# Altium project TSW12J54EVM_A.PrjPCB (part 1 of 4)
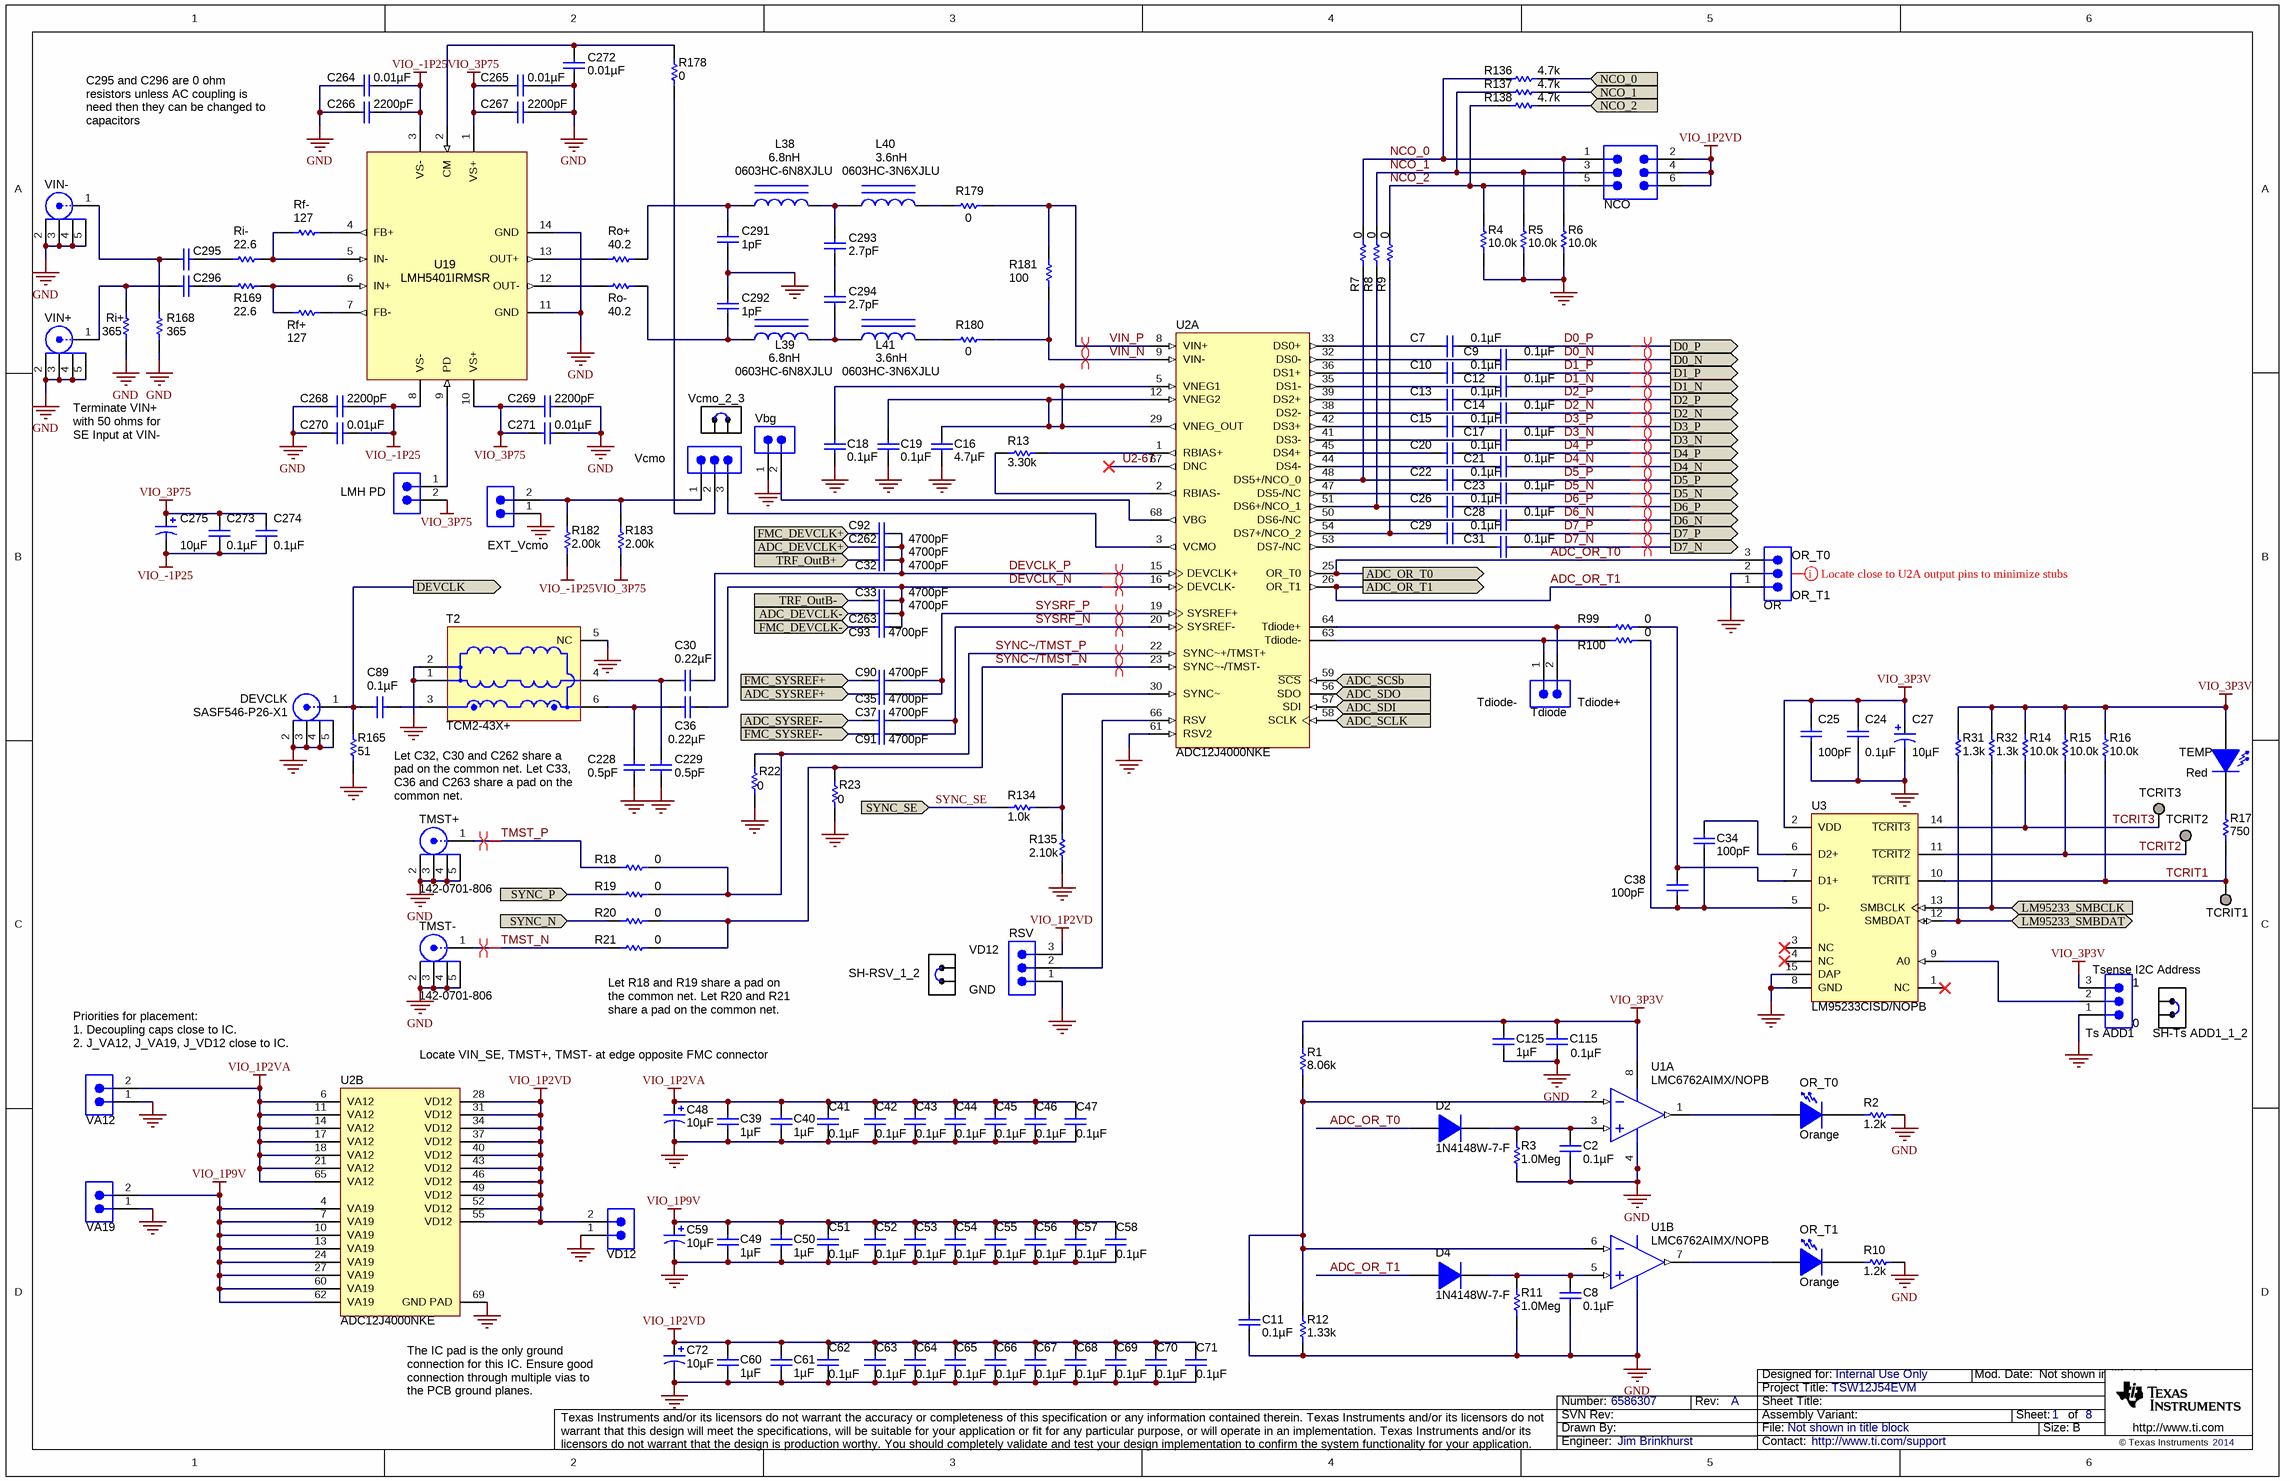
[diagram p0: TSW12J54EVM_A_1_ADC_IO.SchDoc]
CopyrightYear: 2014; Drawn By: Jim Brinkhurst; PCB_LAYOUT: Bob Holtz; PCB_REV: A; PRJ_Customer: Internal Use Only; PRJ_ENGINEER: Jim Brinkhurst; PRJ_NUMBER: 6586307; PRJ_Title: TSW12J54EVM; SCH_Rev: A; TechSupport: http://www.ti.com/support
8 sheets, 655 parts. Net scope: global (net labels, ports and power ports of the same name join across sheets).
Board file: TSW12J54EVM_A.PcbDoc
Sheets:
  TSW12J54EVM_A_1_ADC_IO.SchDoc
  TSW12J54EVM_A_2_FMC.SchDoc
  TSW12J54EVM_A_3_TRF3765.SchDoc
  TSW12J54EVM_A_4_LMK04828.SchDoc
  TSW12J54EVM_A_5_Power.SchDoc
  TSW12J54EVM_A_6_Power.SchDoc
  TSW12J54EVM_A_7_InterfaceControl.SchDoc
  TSW12J54EVM_A_8_Hardware.SchDoc

## Sheet TSW12J54EVM_A_1_ADC_IO.SchDoc
size 431 x 279 mm; Date: Not shown in title block; ApprovedBy: Not shown in title block; CheckedBy: Not shown in title block; Author: Not shown in title block; CompanyName: Not shown in title block; Engineer: Not shown in title block; Organization: Not shown in title block; Address1: Not shown in title block; Address2: Not shown in title block; Address3: Not shown in title block; Address4: Not shown in title block; DocumentNumber: 1; Revision: Use project parameter SCH_Rev; SheetNumber: 1; SheetTotal: 8; PageSetup: Record=PageOptions¦CenterHorizontal=True¦CenterVertical=True¦PrintScale=1.32¦XCorrection=1.00¦YCorrection=1.00¦PrintKind=0¦BorderSize=5000000¦LeftOffset=0¦BottomOffset=0¦Orientation=2¦PaperLength=1000¦PaperWidth=1000¦Scale=100¦PaperSource=15¦PrintQuality=600¦MediaType=1¦DitherType=10¦PaperKind=Letter¦PrintScaleMode=1

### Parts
C2  ValueDisplayed: 0.1µF  [0402L]  (hidden comment: GRM155R71A104KA01D)
C7  ValueDisplayed: 0.1µF  [0201]  (hidden comment: C0603X5R0J104K)
C8  ValueDisplayed: 0.1µF  [0402L]  (hidden comment: GRM155R71A104KA01D)
C9  ValueDisplayed: 0.1µF  [0201]  (hidden comment: C0603X5R0J104K)
C10  ValueDisplayed: 0.1µF  [0201]  (hidden comment: C0603X5R0J104K)
C11  ValueDisplayed: 0.1µF  [0402L]  (hidden comment: GRM155R71A104KA01D)
C12  ValueDisplayed: 0.1µF  [0201]  (hidden comment: C0603X5R0J104K)
C13  ValueDisplayed: 0.1µF  [0201]  (hidden comment: C0603X5R0J104K)
C14  ValueDisplayed: 0.1µF  [0201]  (hidden comment: C0603X5R0J104K)
C15  ValueDisplayed: 0.1µF  [0201]  (hidden comment: C0603X5R0J104K)
C16  ValueDisplayed: 4.7µF  [0402L]  (hidden comment: C1005X5R0J475M050BC)
C17  ValueDisplayed: 0.1µF  [0201]  (hidden comment: C0603X5R0J104K)
C18  ValueDisplayed: 0.1µF  [0402L]  (hidden comment: C1005X5R1A104K)
C19  ValueDisplayed: 0.1µF  [0402L]  (hidden comment: C1005X5R1A104K)
C20  ValueDisplayed: 0.1µF  [0201]  (hidden comment: C0603X5R0J104K)
C21  ValueDisplayed: 0.1µF  [0201]  (hidden comment: C0603X5R0J104K)
C22  ValueDisplayed: 0.1µF  [0201]  (hidden comment: C0603X5R0J104K)
C23  ValueDisplayed: 0.1µF  [0201]  (hidden comment: C0603X5R0J104K)
C24  ValueDisplayed: 0.1µF  [0603L]  (hidden comment: 0603YC104JAT2A)
C25  ValueDisplayed: 100pF  [0603L]  (hidden comment: 06035A101JAT2A)
C26  ValueDisplayed: 0.1µF  [0201]  (hidden comment: C0603X5R0J104K)
C27  ValueDisplayed: 10µF  [3528-21]  (hidden comment: 293D106X0010B2TE3)
C28  ValueDisplayed: 0.1µF  [0201]  (hidden comment: C0603X5R0J104K)
C29  ValueDisplayed: 0.1µF  [0201]  (hidden comment: C0603X5R0J104K)
C30  ValueDisplayed: 0.22µF  [0201]  (hidden comment: C0603X5R0J224M)
C31  ValueDisplayed: 0.1µF  [0201]  (hidden comment: C0603X5R0J104K)
C32  ValueDisplayed: 4700pF  [0201]  (hidden comment: GRM033R61A472KA01D)
C33  ValueDisplayed: 4700pF  [0201]  (hidden comment: GRM033R61A472KA01D)
C34  ValueDisplayed: 100pF  [0603L]  (hidden comment: 06035A101JAT2A)
C35  ValueDisplayed: 4700pF  [0201]  (hidden comment: GRM033R61A472KA01D)
C36  ValueDisplayed: 0.22µF  [0201]  (hidden comment: C0603X5R0J224M)
C37  ValueDisplayed: 4700pF  [0201]  (hidden comment: GRM033R61A472KA01D)
C38  ValueDisplayed: 100pF  [0603L]  (hidden comment: 06035A101JAT2A)
C39  ValueDisplayed: 1µF  [0603L]  (hidden comment: C1608X5R1A105K)
C40  ValueDisplayed: 1µF  [0603L]  (hidden comment: C1608X5R1A105K)
C41  ValueDisplayed: 0.1µF  [0201]  (hidden comment: C0603X5R0J104K)
C42  ValueDisplayed: 0.1µF  [0201]  (hidden comment: C0603X5R0J104K)
C43  ValueDisplayed: 0.1µF  [0201]  (hidden comment: C0603X5R0J104K)
C44  ValueDisplayed: 0.1µF  [0201]  (hidden comment: C0603X5R0J104K)
C45  ValueDisplayed: 0.1µF  [0201]  (hidden comment: C0603X5R0J104K)
C46  ValueDisplayed: 0.1µF  [0201]  (hidden comment: C0603X5R0J104K)
C47  ValueDisplayed: 0.1µF  [0201]  (hidden comment: C0603X5R0J104K)
C48  ValueDisplayed: 10µF  [3528-21]  (hidden comment: 293D106X0010B2TE3)
C49  ValueDisplayed: 1µF  [0603L]  (hidden comment: C1608X5R1A105K)
C50  ValueDisplayed: 1µF  [0603L]  (hidden comment: C1608X5R1A105K)
C51  ValueDisplayed: 0.1µF  [0201]  (hidden comment: C0603X5R0J104K)
C52  ValueDisplayed: 0.1µF  [0201]  (hidden comment: C0603X5R0J104K)
C53  ValueDisplayed: 0.1µF  [0201]  (hidden comment: C0603X5R0J104K)
C54  ValueDisplayed: 0.1µF  [0201]  (hidden comment: C0603X5R0J104K)
C55  ValueDisplayed: 0.1µF  [0201]  (hidden comment: C0603X5R0J104K)
C56  ValueDisplayed: 0.1µF  [0201]  (hidden comment: C0603X5R0J104K)
C57  ValueDisplayed: 0.1µF  [0201]  (hidden comment: C0603X5R0J104K)
C58  ValueDisplayed: 0.1µF  [0201]  (hidden comment: C0603X5R0J104K)
C59  ValueDisplayed: 10µF  [3528-21]  (hidden comment: 293D106X0010B2TE3)
C60  ValueDisplayed: 1µF  [0603L]  (hidden comment: C1608X5R1A105K)
C61  ValueDisplayed: 1µF  [0603L]  (hidden comment: C1608X5R1A105K)
C62  ValueDisplayed: 0.1µF  [0201]  (hidden comment: C0603X5R0J104K)
C63  ValueDisplayed: 0.1µF  [0201]  (hidden comment: C0603X5R0J104K)
C64  ValueDisplayed: 0.1µF  [0201]  (hidden comment: C0603X5R0J104K)
C65  ValueDisplayed: 0.1µF  [0201]  (hidden comment: C0603X5R0J104K)
C66  ValueDisplayed: 0.1µF  [0201]  (hidden comment: C0603X5R0J104K)
C67  ValueDisplayed: 0.1µF  [0201]  (hidden comment: C0603X5R0J104K)
C68  ValueDisplayed: 0.1µF  [0201]  (hidden comment: C0603X5R0J104K)
C69  ValueDisplayed: 0.1µF  [0201]  (hidden comment: C0603X5R0J104K)
C70  ValueDisplayed: 0.1µF  [0201]  (hidden comment: C0603X5R0J104K)
C71  ValueDisplayed: 0.1µF  [0201]  (hidden comment: C0603X5R0J104K)
C72  ValueDisplayed: 10µF  [3528-21]  (hidden comment: 293D106X0010B2TE3)
C89  ValueDisplayed: 0.1µF  [0402L]  (hidden comment: C1005X5R1A104K)
C90  ValueDisplayed: 4700pF  [0201]  (hidden comment: GRM033R61A472KA01D)
C91  ValueDisplayed: 4700pF  [0201]  (hidden comment: GRM033R61A472KA01D)
C92  ValueDisplayed: 4700pF  [0201]  (hidden comment: GRM033R61A472KA01D)
C93  ValueDisplayed: 4700pF  [0201]  (hidden comment: GRM033R61A472KA01D)
C115  ValueDisplayed: 0.1µF  [0603L]  (hidden comment: 0603YC104JAT2A)
C125  ValueDisplayed: 1µF  [0603L]  (hidden comment: C1608X5R1A105K)
C228  ValueDisplayed: 0.5pF  [0402L]  (hidden comment: 500R07S0R5BV4T)
C229  ValueDisplayed: 0.5pF  [0402L]  (hidden comment: 500R07S0R5BV4T)
C262  ValueDisplayed: 4700pF  [0201]  (hidden comment: GRM033R61A472KA01D)
C263  ValueDisplayed: 4700pF  [0201]  (hidden comment: GRM033R61A472KA01D)
C264  ValueDisplayed: 0.01µF  [0306]  (hidden comment: LLL185R71E103MA01L)
C265  ValueDisplayed: 0.01µF  [0306]  (hidden comment: LLL185R71E103MA01L)
C266  ValueDisplayed: 2200pF  [0306]  (hidden comment: LLL185R71H222MA01L)
C267  ValueDisplayed: 2200pF  [0306]  (hidden comment: LLL185R71H222MA01L)
C268  ValueDisplayed: 2200pF  [0306]  (hidden comment: LLL185R71H222MA01L)
C269  ValueDisplayed: 2200pF  [0306]  (hidden comment: LLL185R71H222MA01L)
C270  ValueDisplayed: 0.01µF  [0306]  (hidden comment: LLL185R71E103MA01L)
C271  ValueDisplayed: 0.01µF  [0306]  (hidden comment: LLL185R71E103MA01L)
C272  ValueDisplayed: 0.01µF  [0402L]  (hidden comment: C1005X7R1E103K)
C273  ValueDisplayed: 0.1µF  [0402L]  (hidden comment: C1005X5R1A104K)
C274  ValueDisplayed: 0.1µF  [0402L]  (hidden comment: C1005X5R1A104K)
C275  ValueDisplayed: 10µF  [3216-18]  (hidden comment: TPSA106K010R0900)
C291  ValueDisplayed: 1pF  [0402L]  (hidden comment: GRM1555C1H1R0CA01D)
C292  ValueDisplayed: 1pF  [0402L]  (hidden comment: GRM1555C1H1R0CA01D)
C293  ValueDisplayed: 2.7pF  [0402L]  (hidden comment: GRM1555C1H2R7CA01D)
C294  ValueDisplayed: 2.7pF  [0402L]  (hidden comment: GRM1555C1H2R7CA01D)
C295  Used in BOM report  [0402L]  (value not drawn)
C296  Used in BOM report  [0402L]  (value not drawn)
D2  1N4148W-7-F  [SOD-123]
D4  1N4148W-7-F  [SOD-123]
DEVCLK  SASF546-P26-X1  [CONN_LTI_SASF546-P26-X1]
EXT_Vcmo  TSW-102-07-G-S  [TSW-102-07-G-S]  (value not drawn)
L38  0603HC-6N8XJLU  ValueDisplayed: 6.8nH  [0603HC]
L39  0603HC-6N8XJLU  ValueDisplayed: 6.8nH  [0603HC]
L40  0603HC-3N6XJLU  ValueDisplayed: 3.6nH  [0603HC]
L41  0603HC-3N6XJLU  ValueDisplayed: 3.6nH  [0603HC]
LMH_PD  TSW-102-07-G-S  [TSW-102-07-G-S]  (value not drawn)
NCO  TSW-103-07-G-D  [TSW-103-07-G-D]  (value not drawn)
OR  TSW-103-07-G-S  [TSW-103-07-G-S]  (value not drawn)
OR_T0  value Orange  [LED_LTST-C190]  (hidden comment: LTST-C190KFKT)
OR_T1  value Orange  [LED_LTST-C190]  (hidden comment: LTST-C190KFKT)
R1  value 8.06k  [0402L]  (hidden comment: CRCW04028K06FKED)
R2  value 1.2k  [0402L]  (hidden comment: CRCW04021K20JNED)
R3  value 1.0Meg  [0402L]  (hidden comment: CRCW04021M00JNED)
R4  value 10.0k  [0603L]  (hidden comment: CRCW060310K0FKEA)
R5  value 10.0k  [0603L]  (hidden comment: CRCW060310K0FKEA)
R6  value 10.0k  [0603L]  (hidden comment: CRCW060310K0FKEA)
R7  value 0  [0201]  (hidden comment: ERJ-1GE0R00C)
R8  value 0  [0201]  (hidden comment: ERJ-1GE0R00C)
R9  value 0  [0201]  (hidden comment: ERJ-1GE0R00C)
R10  value 1.2k  [0402L]  (hidden comment: CRCW04021K20JNED)
R11  value 1.0Meg  [0402L]  (hidden comment: CRCW04021M00JNED)
R12  value 1.33k  [0402L]  (hidden comment: CRCW04021K33FKED)
R13  value 3.30k  [0603L]  (hidden comment: RG1608P-332-B-T5)
R14  value 10.0k  [0603L]  (hidden comment: CRCW060310K0FKEA)
R15  value 10.0k  [0603L]  (hidden comment: CRCW060310K0FKEA)
R16  value 10.0k  [0603L]  (hidden comment: CRCW060310K0FKEA)
R17  value 750  [0603L]  (hidden comment: RC0603JR-07750RL)
R18  value 0  [0201]  (hidden comment: ERJ-1GE0R00C)
R19  value 0  [0201]  (hidden comment: ERJ-1GE0R00C)
R20  value 0  [0201]  (hidden comment: ERJ-1GE0R00C)
R21  value 0  [0201]  (hidden comment: ERJ-1GE0R00C)
R22  value 0  [0201]  (hidden comment: ERJ-1GE0R00C)
R23  value 0  [0201]  (hidden comment: ERJ-1GE0R00C)
R31  value 1.3k  [0603L]  (hidden comment: RC0603JR-071K3L)
R32  value 1.3k  [0603L]  (hidden comment: RC0603JR-071K3L)
R99  value 0  [0603L]  (hidden comment: ERJ-3GEY0R00V)
R100  value 0  [0603L]  (hidden comment: ERJ-3GEY0R00V)
R134  value 1.0k  [0603L]  (hidden comment: RC0603JR-071KL)
R135  value 2.10k  [0603L]  (hidden comment: CRCW06032K10FKEA)
R136  value 4.7k  [0603L]  (hidden comment: CRCW06034K70JNEA)
R137  value 4.7k  [0603L]  (hidden comment: CRCW06034K70JNEA)
R138  value 4.7k  [0603L]  (hidden comment: CRCW06034K70JNEA)
R165  value 51  [0402L]  (hidden comment: CRCW040251R0JNED)
R168  ValueDisplayed: 365  [0402L]  (hidden comment: CRCW0402365RFKED)
R169  ValueDisplayed: 22.6  [0402L]  (hidden comment: CRCW040222R6FKED)
R178  value 0  [0402L]  (hidden comment: CRCW04020000Z0ED)
R179  value 0  [0402L]  (hidden comment: CRCW04020000Z0ED)
R180  value 0  [0402L]  (hidden comment: CRCW04020000Z0ED)
R181  value 100  [0402L]  (hidden comment: CRCW0402100RFKED)
R182  ValueDisplayed: 2.00k  [0402L]  (hidden comment: CRCW04022K00FKED)
R183  ValueDisplayed: 2.00k  [0402L]  (hidden comment: CRCW04022K00FKED)
Rf+  ValueDisplayed: 127  [0402L]  (hidden comment: CRCW0402127RFKED)
Rf-  ValueDisplayed: 127  [0402L]  (hidden comment: CRCW0402127RFKED)
Ri+  ValueDisplayed: 365  [0402L]  (hidden comment: CRCW0402365RFKED)
Ri-  ValueDisplayed: 22.6  [0402L]  (hidden comment: CRCW040222R6FKED)
Ro+  value 40.2  [0402L]  (hidden comment: CRCW040240R2FKED)
Ro-  value 40.2  [0402L]  (hidden comment: CRCW040240R2FKED)
RSV  TSW-103-07-G-S  [TSW-103-07-G-S]  (value not drawn)
SH-RSV_1_2  969102-0000-DA  [SNT-100-BK-G]  (value not drawn)
SH-Ts_ADD1_1_2  969102-0000-DA  [SNT-100-BK-G]  (value not drawn)
T2  TCM2-43X+  [Mini-Circuits-DB1627]
TCRIT1  TESTPOINT  [TESTPOINT]  (value not drawn)  (no BOM)
TCRIT2  TESTPOINT  [TESTPOINT]  (value not drawn)  (no BOM)
TCRIT3  TESTPOINT  [TESTPOINT]  (value not drawn)  (no BOM)
Tdiode  TSW-102-07-G-S  [TSW-102-07-G-S]  (value not drawn)
TEMP  value Red  [LED_LTST-C170]  (hidden comment: LTST-C170KRKT)
TMST+  142-0701-806  [Johnson_142-0701-80x]
TMST-  142-0701-806  [Johnson_142-0701-80x]
Ts_ADD1  TSW-103-07-G-S  [TSW-103-07-G-S]  (value not drawn)
U1  LMC6762AIMX/NOPB  [M08A_L]  (parts A,B of 2)
U2  ADC12J4000NKE  [RLY0068A]  (parts A,B of 2)
U3  LM95233CISD/NOPB  [SDA14B]
U19  LMH5401IRMSR  [RMS0014A]
VA12  TSW-102-07-G-S  [TSW-102-07-G-S]  (value not drawn)
VA19  TSW-102-07-G-S  [TSW-102-07-G-S]  (value not drawn)
Vbg  TSW-102-07-G-S  [TSW-102-07-G-S]  (value not drawn)
Vcmo  TSW-103-07-G-S  [TSW-103-07-G-S]  (value not drawn)
Vcmo_2_3  969102-0000-DA  [SNT-100-BK-G]  (value not drawn)
VD12  TSW-102-07-G-S  [TSW-102-07-G-S]  (value not drawn)
VIN+  142-0701-231  [Johnson_142-0701-231]  (value not drawn)
VIN-  142-0701-231  [Johnson_142-0701-231]  (value not drawn)

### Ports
ADC_DEVCLK+ (in), ADC_DEVCLK- (in), ADC_OR_T0 (out), ADC_OR_T1 (out), ADC_SCLK (in), ADC_SCSb (in), ADC_SDI (in), ADC_SDO (out), ADC_SYSREF+, ADC_SYSREF-, D0_N (out), D0_P (out), D1_N (out), D1_P (out), D2_N (out), D2_P (out), D3_N (out), D3_P (out), D4_N (out), D4_P (out), D5_N (out), D5_P (out), D6_N (out), D6_P (out), D7_N (out), D7_P (out), DEVCLK (out), FMC_DEVCLK+ (in), FMC_DEVCLK- (in), FMC_SYSREF+, FMC_SYSREF-, LM95233_SMBCLK (in), LM95233_SMBDAT (bidir), NCO_0 (in), NCO_1 (in), NCO_2 (in), SYNC_N (in), SYNC_P (in), SYNC_SE (in), TRF_OutB+ (in), TRF_OutB- (in)

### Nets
GND: C2.2 C8.2 C11.2 C16.1 C18.1 C19.1 C24.2 C25.2 C27.2(-) C39.2 C40.2 C41.1 C42.1 C43.1 C44.1 C45.1 C46.1 C47.1 C48.2(-) C49.2 C50.2 C51.1 C52.1 C53.1 C54.1 C55.1 C56.1 C57.1 C58.1 C59.2(-) C60.2 C61.2 C62.1 C63.1 C64.1 C65.1 C66.1 C67.1 C68.1 C69.1 C70.1 C71.1 C72.2(-) C115.2 C125.2 C228.2 C229.2 C264.1 C265.2 C266.2 C267.1 C268.2 C269.1 C270.1 C271.2 C272.1 C291.2 C292.1 DEVCLK.2 DEVCLK.3 DEVCLK.4 DEVCLK.5 EXT_Vcmo.1 OR.2 R2.2 R3.1 R4.1 R5.1 R6.1 R10.2 R11.1 R12.1 R22.2 R23.2 R135.1 R165.1 R168.1 Ri+.1 RSV.1 T2.1 T2.2 T2.5(NC) TMST+.2 TMST+.3 TMST+.4 TMST+.5 TMST-.2 TMST-.3 TMST-.4 TMST-.5 Ts_ADD1.1 U1.4(V-) U2.61(RSV2) U2.69(GND_PAD) U3.8(GND) U3.15(DAP) U19.11(GND) U19.14(GND) VA12.1 VA19.1 Vbg.1 VD12.1 VIN+.2 VIN+.3 VIN+.4 VIN+.5 VIN-.2 VIN-.3 VIN-.4 VIN-.5
VIO_1P2VA: C39.1 C40.1 C41.2 C42.2 C43.2 C44.2 C45.2 C46.2 C47.2 C48.1(+) U2.6(VA12) U2.11(VA12) U2.14(VA12) U2.17(VA12) U2.18(VA12) U2.21(VA12) U2.65(VA12) VA12.2
VIO_1P2VD: C60.1 C61.1 C62.2 C63.2 C64.2 C65.2 C66.2 C67.2 C68.2 C69.2 C70.2 C71.2 C72.1(+) NCO.2 NCO.4 NCO.6 RSV.3 U2.28(VD12) U2.31(VD12) U2.34(VD12) U2.37(VD12) U2.40(VD12) U2.43(VD12) U2.46(VD12) U2.49(VD12) U2.52(VD12) U2.55(VD12) VD12.2
VIO_1P9V: C49.1 C50.1 C51.2 C52.2 C53.2 C54.2 C55.2 C56.2 C57.2 C58.2 C59.1(+) U2.4(VA19) U2.7(VA19) U2.10(VA19) U2.13(VA19) U2.24(VA19) U2.27(VA19) U2.60(VA19) U2.62(VA19) VA19.2
VIO_3P3V: C24.1 C25.1 C27.1(+) C115.1 C125.1 R1.2 R14.2 R15.2 R16.2 R31.2 R32.2 TEMP.1(A) Ts_ADD1.3 U1.8(V+) U3.2(VDD)
VIO_3P75: C265.1 C267.2 C269.2 C271.1 C273.1 C274.1 C275.1(+) LMH_PD.2 R183.1 U19.1(VS+) U19.10(VS+)
VIO_-1P25: C264.2 C266.1 C268.1 C270.2 C273.2 C274.2 C275.2(-) R182.1 U19.3(VS-) U19.8(VS-)
ADC_OR_T0: D2.2(A) OR.3 U2.25(OR_T0) ; port ADC_OR_T0
ADC_OR_T1: D4.2(A) OR.1 U2.26(OR_T1) ; port ADC_OR_T1
D0_N: C9.1 ; port D0_N
D0_P: C7.1 ; port D0_P
D1_N: C12.1 ; port D1_N
D1_P: C10.1 ; port D1_P
D2_N: C14.1 ; port D2_N
D2_P: C13.1 ; port D2_P
D3_N: C17.1 ; port D3_N
D3_P: C15.1 ; port D3_P
D4_N: C21.1 ; port D4_N
D4_P: C20.1 ; port D4_P
D5_N: C23.1 ; port D5_N
D5_P: C22.1 ; port D5_P
D6_N: C28.1 ; port D6_N
D6_P: C26.1 ; port D6_P
D7_N: C31.1 ; port D7_N
D7_P: C29.1 ; port D7_P
DEV_CLK_N: C263.2 ; port ADC_DEVCLK-
DEV_CLK_P: C262.2 ; port ADC_DEVCLK+
DEVCLK_N: C33.1 C36.1 C93.1 C263.1 U2.16(DEVCLK-)
DEVCLK_P: C30.1 C32.1 C92.1 C262.1 U2.15(DEVCLK+)
FMC_DEVCLK_N: C93.2 ; port FMC_DEVCLK-
FMC_DEVCLK_P: C92.2 ; port FMC_DEVCLK+
FMC_SYSREF_N: C91.2 ; port FMC_SYSREF-
FMC_SYSREF_P: C90.2 ; port FMC_SYSREF+
NCO_0: NCO.1 R6.2 R7.1 R136.1
NCO_1: NCO.3 R5.2 R8.1 R137.1
NCO_2: NCO.5 R4.2 R9.1 R138.1
SYNC_N: R20.2 ; port SYNC_N
SYNC_P: R19.2 ; port SYNC_P
SYNC_SE: R134.1 ; port SYNC_SE
SYNC~/TMST_N: R20.1 R21.1 R23.1 U2.23(SYNC~-/TMST-)
SYNC~/TMST_P: R18.1 R19.1 R22.1 U2.22(SYNC~+/TMST+)
SYSREFTX_N: C37.2 ; port ADC_SYSREF-
SYSREFTX_P: C35.2 ; port ADC_SYSREF+
SYSRF_N: C37.1 C91.1 U2.20(SYSREF-)
SYSRF_P: C35.1 C90.1 U2.19(SYSREF+)
TCRIT1: R16.1 R17.1 TCRIT1.1 U3.10(~{TCRIT1})
TCRIT2: R15.1 TCRIT2.1 U3.11(~{TCRIT2})
TCRIT3: R14.1 TCRIT3.1 U3.14(~{TCRIT3})
TMST_N: R21.2 TMST-.1
TMST_P: R18.2 TMST+.1
TRF_OutB_N: C33.2 ; port TRF_OutB-
TRF_OutB_P: C32.2 ; port TRF_OutB+
U2-67: U2.67(DNC)
VIN_N: R180.2 R181.1 U2.9(VIN-)
VIN_P: R179.2 R181.2 U2.8(VIN+)
NetC2_1: C2.1 D2.1(K) R3.2 U1.3(INA+)
NetC7_2: C7.2 U2.33(DS0+)
NetC8_1: C8.1 D4.1(K) R11.2 U1.5(INB+)
NetC9_2: C9.2 U2.32(DS0-)
NetC10_2: C10.2 U2.36(DS1+)
NetC11_1: C11.1 R1.1 R12.2 U1.2(INA-) U1.6(INB-)
NetC12_2: C12.2 U2.35(DS1-)
NetC13_2: C13.2 U2.39(DS2+)
NetC14_2: C14.2 U2.38(DS2-)
NetC15_2: C15.2 U2.42(DS3+)
NetC16_2: C16.2 C18.2 C19.2 U2.5(VNEG1) U2.12(VNEG2) U2.29(VNEG_OUT)
NetC17_2: C17.2 U2.41(DS3-)
NetC20_2: C20.2 U2.45(DS4+)
NetC21_2: C21.2 U2.44(DS4-)
NetC22_2: C22.2 R7.2 U2.48(DS5+/NCO_0)
NetC23_2: C23.2 U2.47(DS5-/NC)
NetC26_2: C26.2 R8.2 U2.51(DS6+/NCO_1)
NetC28_2: C28.2 U2.50(DS6-/NC)
NetC29_2: C29.2 R9.2 U2.54(DS7+/NCO_2)
NetC30_2: C30.2 C229.1 T2.4
NetC31_2: C31.2 U2.53(DS7-/NC)
NetC34_1: C34.1 U3.6(D2+)
NetC34_2: C34.2 C38.2 R100.2 U3.5(D-)
NetC36_2: C36.2 C228.1 T2.6
NetC38_1: C38.1 R99.2 U3.7(D1+)
NetC87_2: C89.1 DEVCLK.1 R165.2 ; port DEVCLK
NetC89_2: C89.2 T2.3
NetC272_2: C272.2 R178.2 U19.2(CM)
NetC291_1: C291.1 L38.1 Ro+.2
NetC292_2: C292.2 L39.1 Ro-.2
NetC293_1: C293.1 L38.2 L40.1
NetC293_2: C293.2 C294.1
NetC294_2: C294.2 L39.2 L41.1
NetC295_1: C295.1 Ri-.1
NetC295_2: C295.2 R168.2 VIN-.1
NetC296_1: C296.1 R169.2
NetC296_2: C296.2 Ri+.2 VIN+.1
NetEXT_Vcmo_2: EXT_Vcmo.2 R182.2 R183.2 Vcmo.1
NetFMC_RX1_E12: R136.2 ; port NCO_0
NetFMC_RX1_E13: R137.2 ; port NCO_1
NetFMC_RX1_E36: R138.2 ; port NCO_2
NetL40_2: L40.2 R179.1
NetL41_2: L41.2 R180.1
NetLMH_PD_1: LMH_PD.1 U19.9(PD)
NetOR_T0_1: OR_T0.1(A) U1.1(OUTA)
NetOR_T0_2: OR_T0.2(K) R2.1
NetOR_T1_1: OR_T1.1(A) U1.7(OUTB)
NetOR_T1_2: OR_T1.2(K) R10.1
NetR13_1: R13.1 U2.2(RBIAS-)
NetR13_2: R13.2 U2.1(RBIAS+)
NetR17_2: R17.2 TEMP.2(K)
NetR31_1: R31.1 U3.12(SMBDAT) ; port LM95233_SMBDAT
NetR32_1: R32.1 U3.13(SMBCLK) ; port LM95233_SMBCLK
NetR54_1: U2.59(~{SCS}) ; port ADC_SCSb
NetR55_1: U2.56(SDO) ; port ADC_SDO
NetR57_1: U2.57(SDI) ; port ADC_SDI
NetR58_1: U2.58(SCLK) ; port ADC_SCLK
NetR99_1: R99.1 Tdiode.2 U2.64(Tdiode+)
NetR100_1: R100.1 Tdiode.1 U2.63(Tdiode-)
NetR134_2: R134.2 R135.2 U2.30(SYNC~)
NetR169_1: R169.1 Rf+.2 U19.6(IN+)
NetR178_1: R178.1 Vcmo.2
NetRf+_1: Rf+.1 U19.7(FB-)
NetRf-_1: Rf-.1 U19.4(FB+)
NetRf-_2: Rf-.2 Ri-.2 U19.5(IN-)
NetRo+_1: Ro+.1 U19.13(OUT+)
NetRo-_1: Ro-.1 U19.12(OUT-)
NetRSV_2: RSV.2 U2.66(RSV)
NetTs_ADD1_2: Ts_ADD1.2 U3.9(A0)
NetU2_3: U2.3(VCMO) Vcmo.3
NetU2_68: U2.68(VBG) Vbg.2

Not connected (* = marked no-connect by the designer): U3 1(NC)* 3(NC)* 4(NC)*

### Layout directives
differential pair: D0_N, D0_P, D1_N, D1_P, D2_N, D2_P, D3_N, D3_P, D4_N, D4_P, D5_N, D5_P, D6_N, D6_P, D7_N, D7_P, DEVCLK_N, DEVCLK_P, SYNC~/TMST_N, SYNC~/TMST_P, SYSRF_N, SYSRF_P, TMST_N, TMST_P, VIN_N, VIN_P
rule Undefined: (no net found under the mark)

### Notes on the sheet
- C295 and C296 are 0 ohm resistors unless AC coupling is need then they can be changed to capacitors
- Terminate VIN+ with 50 ohms for SE Input at VIN-
- (near OR) OR_T0
- (near OR) OR_T1
- (near Tdiode) Tdiode-
- (near Tdiode) Tdiode+
- Let C32, C30 and C262 share a pad on the common net. Let C33, C36 and C263 share a pad on the common net.
- VD12
- (near Ts_ADD1) Tsense I2C Address
- (near R21) Let R18 and R19 share a pad on the common net. Let R20 and R21 share a pad on the common net.
- GND
- (near SH-Ts_ADD1_1_2) 1
- (near SH-Ts_ADD1_1_2) 0
- (near VA12) Priorities for placement:
  1. Decoupling caps close to IC.
  2. J_VA12, J_VA19, J_VD12 close to IC.
- Locate VIN_SE, TMST+, TMST- at edge opposite FMC connector
- (near U2) The IC pad is the only ground connection for this IC. Ensure good connection through multiple vias to the PCB ground planes.

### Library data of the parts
C2 C8 C11 = GRM155R71A104KA01D: CAP, CERM, 0.1uF, 10V, +/-10%, X7R, 0402; Manufacturer: MuRata; Polarized: N; CompType: Capacitor; U/M: EA; Cap_F: 0.0000001; Tolerance_%: 10; TaMin_C: -55; TaMax_C: 125; Cap_Case: 0402
C7 C9 C10 C12-C15 C17 C20-C23 C26 C28 C29 C31 C41-C47 C51-C58 C62-C71 = Capacitor: CAP, CERM, 0.1uF, 6.3V, X5R, 10%, 0201; Manufacturer: TDK; Polarized: N; U/M: EA
C16 = C1005X5R0J475M050BC: CAP, CERM, 4.7uF, 6.3V, +/-20%, X5R, 0402; Manufacturer: TDK; Polarized: N; CompType: Capacitor; U/M: EA; Cap_F: 0.0000047; Tolerance_%: 20; Value1: Unknown; VDC_V: 6.3; TaMin_C: -55; TaMax_C: 85; Cap_Case: 0402
C18 C19 C89 C273 C274 = C1005X5R1A104K: CAP, CERM, 0.1uF, 10V, +/-10%, X5R, 0402; Manufacturer: TDK; Polarized: N; CompType: Capacitor; U/M: EA; Cap_F: 0.0000001; Tolerance_%: 10; ESR_Ohm: 0.0186; Value1: 0.0186 ohm; TaMin_C: -55; TaMax_C: 85; Cap_Case: 0402
C24 C115 = 0603YC104JAT2A: CAP, CERM, 0.1uF, 16V, +/-5%, X7R, 0603; Manufacturer: AVX; Polarized: N; CompType: Capacitor; U/M: EA; Cap_F: 0.0000001; Tolerance_%: 5; ESR_Ohm: 0.039; Value1: 0.039 ohm; VDC_V: 16; TaMin_C: -55; TaMax_C: 125; Cap_Case: 0603
C25 C34 C38 = 06035A101JAT2A: CAP, CERM, 100pF, 50V, +/-5%, C0G/NP0, 0603; Manufacturer: AVX; Polarized: N; CompType: Capacitor; U/M: EA; Cap_F: 0.0000000001; Tolerance_%: 5; ESR_Ohm: 0.119; Value1: 0.119 ohm; VDC_V: 50; TaMin_C: -55; TaMax_C: 125; Cap_Case: 0603
C27 C48 C59 C72 = 293D106X0010B2TE3: CAP, TANT, 10uF, 10V, +/-20%, 2.5 ohm, 3528-21 SMD; Manufacturer: Vishay-Sprague; Polarized: Y; CompType: Capacitor; U/M: EA; Cap_F: 0.00001; Tolerance_%: 20; Value1: 2.5 ohm; VDC_V: 10; ESR_Ohm: 2.5; IRMS_A: 0.18; TaMin_C: -55; TaMax_C: 125; Cap_Case: B
C30 C36 = C0603X5R0J224M: CAP, CERM, 0.22uF, 6.3V, +/-20%, X5R, 0201; Manufacturer: TDK; Polarized: N; CompType: Capacitor; U/M: EA; Cap_F: 0.00000022; Tolerance_%: 20; Value1: Unknown; VDC_V: 6.3; TaMin_C: -55; TaMax_C: 85
C32 C33 C35 C37 C90-C93 C262 C263 = GRM033R61A472KA01D: CAP, CERM, 4700pF, 10V, +/-10%, X5R, 0201; Manufacturer: MuRata; Polarized: N; CompType: Capacitor; U/M: EA; Cap_F: 0.0000000047; Tolerance_%: 10; TaMin_C: -55; TaMax_C: 85
C39 C40 C49 C50 C60 C61 C125 = C1608X5R1A105K: CAP, CERM, 1uF, 10V, +/-10%, X5R, 0603; Manufacturer: TDK; Polarized: N; CompType: Capacitor; U/M: EA; Cap_F: 0.000001; Tolerance_%: 10; ESR_Ohm: 0.0057; Value1: 0.0057 ohm; TaMin_C: -55; TaMax_C: 85; Cap_Case: 0603
C228 C229 = GRM155R71A104KA01D: CAP CER 0.5PF 50V NP0 0402; Manufacturer: Johanson Technology Inc; Polarized: N; CompType: Capacitor; U/M: EA; VDC_V: 50; Cap_Case: 0402
C264 C265 C270 C271 = LLL185R71E103MA01L: CAP, CERM, 0.01uF, 25V, +/-20%, X7R, 0306; Manufacturer: MuRata; Polarized: N; CompType: Capacitor; U/M: EA; Cap_F: 0.00000001; Tolerance_%: 20; Value1: Unknown; VDC_V: 25; TaMin_C: -55; TaMax_C: 125
C266-C269 = LLL185R71H222MA01L: CAP, CERM, 2200pF, 50V, +/-20%, X7R, 0306; Manufacturer: MuRata; Polarized: N; CompType: Capacitor; U/M: EA; Cap_F: 0.0000000022; Tolerance_%: 20; Value1: Unknown; VDC_V: 50; TaMin_C: -55; TaMax_C: 125
C272 = C1005X7R1E103K: CAP, CERM, 0.01uF, 25V, +/-10%, X7R, 0402; Manufacturer: TDK; Cap_Case: 0402; ESR_Ohm: 0.0623; Polarized: N; TaMax_C: 125; TaMin_C: -55; Tolerance_%: 10; VDC_V: 25; Cap_F: 10.0E-9; CompType: Capacitor; Value1: 0.0623 ohm
C275 = TPSA106K010R0900: CAP, TA, 10uF, 10V, +/-10%, 0.9 ohm, SMD; Manufacturer: AVX; Polarized: Y; CompType: Capacitor; U/M: EA; Cap_F: 0.00001; Tolerance_%: 10; Value1: 0.9 ohm; ESR_Ohm: 0.9; IRMS_A: 0.26; TaMin_C: -55; TaMax_C: 125; Cap_Case: A
C291 C292 = GRM1555C1H1R0CA01D: CAP, CERM, 1 pF, 50 V, +/- 5%, C0G/NP0, 0402; Manufacturer: MuRata; Polarized: N; CompType: Capacitor; Value: 1pF; U/M: EA; Cap_F: 0.000000000001; Tolerance_%: 5; Value1: Unknown; VDC_V: 50; Value2: 50V; TaMin_C: -55; TaMax_C: 125; Cap_Case: 0402
C293 C294 = GRM1555C1H2R7CA01D: CAP, CERM, 2.7 pF, 50 V, +/- 5%, C0G/NP0, 0402; Manufacturer: MuRata; Polarized: N; CompType: Capacitor; Value: 2.7pF; U/M: EA; Cap_F: 0.0000000000027; Tolerance_%: 5; Value1: Unknown; VDC_V: 50; Value2: 50V; TaMin_C: -55; TaMax_C: 125; Cap_Case: 0402
C295 C296 = Capacitor: CAP, CERM, xxxF, xxV, [TempCo], xx%, [PackageReference]; Polarized: N; U/M: EA
D2 D4 = 1N4148W-7-F: Diode, Ultrafast, 100V, 0.15A, SOD-123; Manufacturer: Diodes Inc.; U/M: EA; Vf_V: 1.25; Io_A: 0.15; Vr_V: 100; TJmax_C: 150; Value: 1.25V
DEVCLK = SASF546-P26-X1: Connector, SMA,Vertical, Thru hole w/SMT center pin; Manufacturer: Lighthorse Technologies; U/M: EA
EXT_Vcmo LMH_PD Tdiode VA12 VA19 Vbg VD12 = TSW-102-07-G-S: Header, TH, 100mil, 2x1, Gold plated, 230 mil above insulator; Manufacturer: Samtec, Inc.; U/M: EA
L38 L39 = 0603HC-6N8XJLU: Inductor, Wirewound, Ceramic, 6.8 nH, 2.1 A, 0.054 ohm, SMD; Manufacturer: Coilcraft; Value: 6.8nH; Ind_H: 6.8E-9; Imax_A: 2.1; Irms: 2.4A @ 20C rise; DCR_ohm: 0.054; Value2: 2.1A
L40 L41 = 0603HC-3N6XJLU: Inductor, Wirewound, Ceramic, 3.6 nH, 2.3 A, 0.048 ohm, SMD; Manufacturer: Coilcraft; Value: 3.6nH; Ind_H: 3.6E-9; Imax_A: 2.3; Irms: 2.4A @ 20C rise; DCR_ohm: 0.048; Value2: 2.3A
NCO = TSW-103-07-G-D: Header, TH, 100mil, 3x2, Gold plated, 230 mil above insulator; Manufacturer: Samtec, Inc.; Alternate Manufacturer: Any; Alternate PartNumber: Equivalent; U/M: EA
OR RSV Ts_ADD1 Vcmo = TSW-103-07-G-S: Header, TH, 100mil, 3x1, Gold plated, 230 mil above insulator; Manufacturer: Samtec, Inc.; Alternate Manufacturer: Any; Alternate PartNumber: Equivalent; U/M: EA
OR_T0 OR_T1 = LTST-C190KFKT: LED, Orange, SMD; Manufacturer: Lite-On; Vf_V: 2; Value2: 2V; Io_A: 0.02; Power_TotalModule: 0.075; Value1: 0.075W; U/M: EA
R1 = CRCW04028K06FKED: RES, 8.06k ohm, 1%, 0.063W, 0402; Manufacturer: Vishay-Dale; CompType: Resistor; Res_ohm: 8060; Value_Code: 8k06; Tolerance_%: 1; Power_W: 0.063; VDC_V: 50; TempCo: 100 ppm/C; EIA_Code: E96; U/M: EA
R2 R10 = CRCW04021K20JNED: RES, 1.2k ohm, 5%, 0.063W, 0402; Manufacturer: Vishay-Dale; CompType: Resistor; Res_ohm: 1200; Value_Code: 1k20; Tolerance_%: 5; Power_W: 0.063; VDC_V: 50; TempCo: 200 ppm/C; EIA_Code: E24; U/M: EA
R3 R11 = CRCW04021M00JNED: RES, 1.0Meg ohm, 5%, 0.063W, 0402; Manufacturer: Vishay-Dale; CompType: Resistor; Res_ohm: 1000000; Value_Code: 1M00; Tolerance_%: 5; Power_W: 0.063; VDC_V: 50; TempCo: 200 ppm/C; EIA_Code: E24; U/M: EA
R4-R6 R14-R16 = CRCW060310K0FKEA: RES, 10.0k ohm, 1%, 0.1W, 0603; Manufacturer: Vishay-Dale; CompType: Resistor; Res_ohm: 10000; Value_Code: 10k0; Tolerance_%: 1; Power_W: 0.1; VDC_V: 75; TempCo: 100 ppm/C; EIA_Code: E96; U/M: EA
R7-R9 R18-R23 = ERJ-1GE0R00C: RES, 0 ohm, 5%, 0.05W, 0201; Manufacturer: Panasonic; CompType: Resistor; Value_Code: 0000; Tolerance_%: 5; Power_W: 0.05; VDC_V: 15; TempCo: 600 ppm/C; EIA_Code: E24; U/M: EA
R12 = CRCW04021K33FKED: RES, 1.33k ohm, 1%, 0.063W, 0402; Manufacturer: Vishay-Dale; CompType: Resistor; Res_ohm: 1330; Value_Code: 1k33; Tolerance_%: 1; Power_W: 0.063; VDC_V: 50; TempCo: 100 ppm/C; EIA_Code: E96; U/M: EA
R13 = RG1608P-332-B-T5: RES, 3.30k ohm, 0.1%, 0.1W, 0603; Manufacturer: Susumu Co Ltd; CompType: Resistor; Res_ohm: 3300; Value_Code: 3k30; Tolerance_%: 0.1; VDC_V: 75; TempCo: 25 ppm/C; U/M: EA
R17 = RC0603JR-07750RL: RES, 750 ohm, 5%, 0.1W, 0603; Manufacturer: Yageo America; CompType: Resistor; Value_Code: 750R; Tolerance_%: 5; Power_W: 0.1; VDC_V: 50; TempCo: 100 ppm/C; EIA_Code: E24; U/M: EA
R31 R32 = RC0603JR-071K3L: RES, 1.3k ohm, 5%, 0.1W, 0603; Manufacturer: Yageo America; CompType: Resistor; Res_ohm: 1300; Value_Code: 1k30; Tolerance_%: 5; Power_W: 0.1; VDC_V: 50; TempCo: 100 ppm/C; EIA_Code: E24; U/M: EA
R99 R100 = ERJ-3GEY0R00V: RES, 0 ohm, 5%, 0.1W, 0603; Manufacturer: Panasonic; CompType: Resistor; Value_Code: 0000; Tolerance_%: 5; Power_W: 0.1; VDC_V: 50; TempCo: 600 ppm/C; EIA_Code: E24; U/M: EA
R134 = RC0603JR-071KL: RES, 1.0k ohm, 5%, 0.1W, 0603; Manufacturer: Yageo America; CompType: Resistor; Res_ohm: 1000; Value_Code: 1k00; Tolerance_%: 5; Power_W: 0.1; VDC_V: 50; TempCo: 100 ppm/C; EIA_Code: E24; U/M: EA
R135 = CRCW06032K10FKEA: RES, 2.10k ohm, 1%, 0.1W, 0603; Manufacturer: Vishay-Dale; CompType: Resistor; Res_ohm: 2100; Value_Code: 2k10; Tolerance_%: 1; Power_W: 0.1; VDC_V: 75; TempCo: 100 ppm/C; EIA_Code: E96; U/M: EA
R136-R138 = CRCW06034K70JNEA: RES, 4.7k ohm, 5%, 0.1W, 0603; Manufacturer: Vishay-Dale; CompType: Resistor; Res_ohm: 4700; Value_Code: 4k70; Tolerance_%: 5; Power_W: 0.1; VDC_V: 75; TempCo: 200 ppm/C; EIA_Code: E24; U/M: EA
R165 = CRCW040251R0JNED: RES, 51 ohm, 5%, 0.063W, 0402; Manufacturer: Vishay-Dale; Alternate Manufacturer: Any; Alternate PartNumber: Equivalent; CompType: Resistor; Value_Code: 51R0; Tolerance_%: 5; Power_W: 0.063; VDC_V: 50; TempCo: 200 ppm/C; EIA_Code: E24; U/M: EA
R168 Ri+ = CRCW0402365RFKED: RES, 365, 1%, 0.063 W, 0402; Manufacturer: Vishay-Dale; CompType: Resistor; Value: 365; Value_Code: 365R; Tolerance_%: 1; Power_W: 0.063; Value2: 0.063W; VDC_V: 50; TempCo: 100 ppm/C; EIA_Code: E96; U/M: EA
R169 Ri- = CRCW040222R6FKED: RES, 22.6, 1%, 0.063 W, 0402; Manufacturer: Vishay-Dale; CompType: Resistor; Value: 22.6; Value_Code: 22R6; Tolerance_%: 1; Power_W: 0.063; Value2: 0.063W; VDC_V: 50; TempCo: 100 ppm/C; EIA_Code: E96; U/M: EA
R178-R180 = CRCW04020000Z0ED: RES, 0 ohm, 5%, 0.063W, 0402; Manufacturer: Vishay-Dale; CompType: Resistor; Value_Code: 0000; Tolerance_%: 5; Power_W: 0.063; VDC_V: 50; TempCo: 200 ppm/C; EIA_Code: E24; U/M: EA
R181 = CRCW0402100RFKED: RES, 100 ohm, 1%, 0.063W, 0402; Manufacturer: Vishay-Dale; CompType: Resistor; Value_Code: 100R; Tolerance_%: 1; Power_W: 0.063; VDC_V: 50; TempCo: 100 ppm/C; EIA_Code: E96; U/M: EA
R182 R183 = CRCW04022K00FKED: RES, 2.00 k, 1%, 0.063 W, 0402; Manufacturer: Vishay-Dale; CompType: Resistor; Value: 2.00k; Res_ohm: 2000; Value_Code: 2k00; Tolerance_%: 1; Power_W: 0.063; Value2: 0.063W; VDC_V: 50; TempCo: 100 ppm/C; EIA_Code: E96; U/M: EA
Rf+ Rf- = CRCW0402127RFKED: RES, 127, 1%, 0.063 W, 0402; Manufacturer: Vishay-Dale; CompType: Resistor; Value: 127; Value_Code: 127R; Tolerance_%: 1; Power_W: 0.063; Value2: 0.063W; VDC_V: 50; TempCo: 100 ppm/C; EIA_Code: E96; U/M: EA
Ro+ Ro- = CRCW040240R2FKED: RES, 40.2 ohm, 1%, 0.063W, 0402; Manufacturer: Vishay-Dale; CompType: Resistor; Value_Code: 40R2; Tolerance_%: 1; Power_W: 0.063; VDC_V: 50; TempCo: 100 ppm/C; EIA_Code: E96; U/M: EA
SH-RSV_1_2 SH-Ts_ADD1_1_2 Vcmo_2_3 = 969102-0000-DA: Shunt, 100mil, Gold plated, Black; Manufacturer: 3M; Alternate Manufacturer: Any; Alternate PartNumber: Equivalent; U/M: EA; Value: 1x2; Note: You can "mate" this to a header by matching the designator.  i.e. use SH-J3 for header J3
T2 = TCM2-43X+: Transformer, RF, 50 ohm, 10 to 4000 MHz, SMT; Manufacturer: Minicircuits; SymbolCreator: a0799628; U/M: EA
TCRIT1-TCRIT3 = TESTPOINT: TEST POINT.  No entry in BOM.
TEMP = LTST-C170KRKT: LED, Red, SMD; Manufacturer: Lite-On; Vf_V: 2; Value2: 2V; Io_A: 20; Value1: W; U/M: EA
TMST+ TMST- = 142-0701-806: Connector, SMT, End launch SMA 50 ohm; Manufacturer: Emerson Network Power; Value: 50 Ohm; U/M: EA
U1 = LMC6762AIMX: Dual Micro-Power Rail-to-Rail Input CMOS Comparator with Push-Pull Output, 8-pin Narrow SOIC; Manufacturer: National Semiconductor; PackageTopMarking: NSZXTT*LMC67*62AIM; PowerWise: N
U2 = ADC12X3500RFLQNOPB: ADC12J4000RLY Ultra-Wideband RF Sampling Subsystem, RLY0068A; Alternate Manufacturer: None; Manufacturer: Texas Instruments; SymbolCreator: a0411947; CompType: IC; U/M: EA
U3 = LM95233CISD/NOPB: Dual Remote Diode and Local Temperature Sensor with SMBus Interface and TruTherm Technology, 14-pin LLP, Pb-Free; Manufacturer: National Semiconductor; PackageTopMarking: NS*UZXYTT*95233CI; PowerWise: Y; CompType: Temp Sensor IC
U19 = LMH5401RMS: 8GHz Ultra Wideband Fully Differential Amplifier, RMS0014A; Alternate Manufacturer: None; Manufacturer: Texas Instruments; SymbolCreator: Altium; CompType: IC; U/M: EA
VIN+ VIN- = 142-0701-231: Connector, TH, SMA; Manufacturer: Emerson Network Power; SymbolCreator: X0208326; U/M: EA

## Sheet TSW12J54EVM_A_2_FMC.SchDoc
size 558 x 431 mm; Date: Not shown in title block; ApprovedBy: Not shown in title block; CheckedBy: Not shown in title block; Author: Not shown in title block; CompanyName: Not shown in title block; Engineer: Not shown in title block; Organization: Not shown in title block; Address1: Not shown in title block; Address2: Not shown in title block; Address3: Not shown in title block; Address4: Not shown in title block; DocumentNumber: 2; Revision: Use project parameter SCH_Rev; SheetNumber: 2; SheetTotal: 8; PageSetup: Record=PageOptions¦CenterHorizontal=True¦CenterVertical=True¦PrintScale=0.62¦XCorrection=1.00¦YCorrection=1.00¦PrintKind=0¦BorderSize=5000000¦LeftOffset=0¦BottomOffset=0¦Orientation=2¦PaperLength=1000¦PaperWidth=1000¦Scale=100¦PaperSource=15¦PrintQuality=600¦MediaType=1¦DitherType=10¦PaperKind=11x17¦PrintScaleMode=1
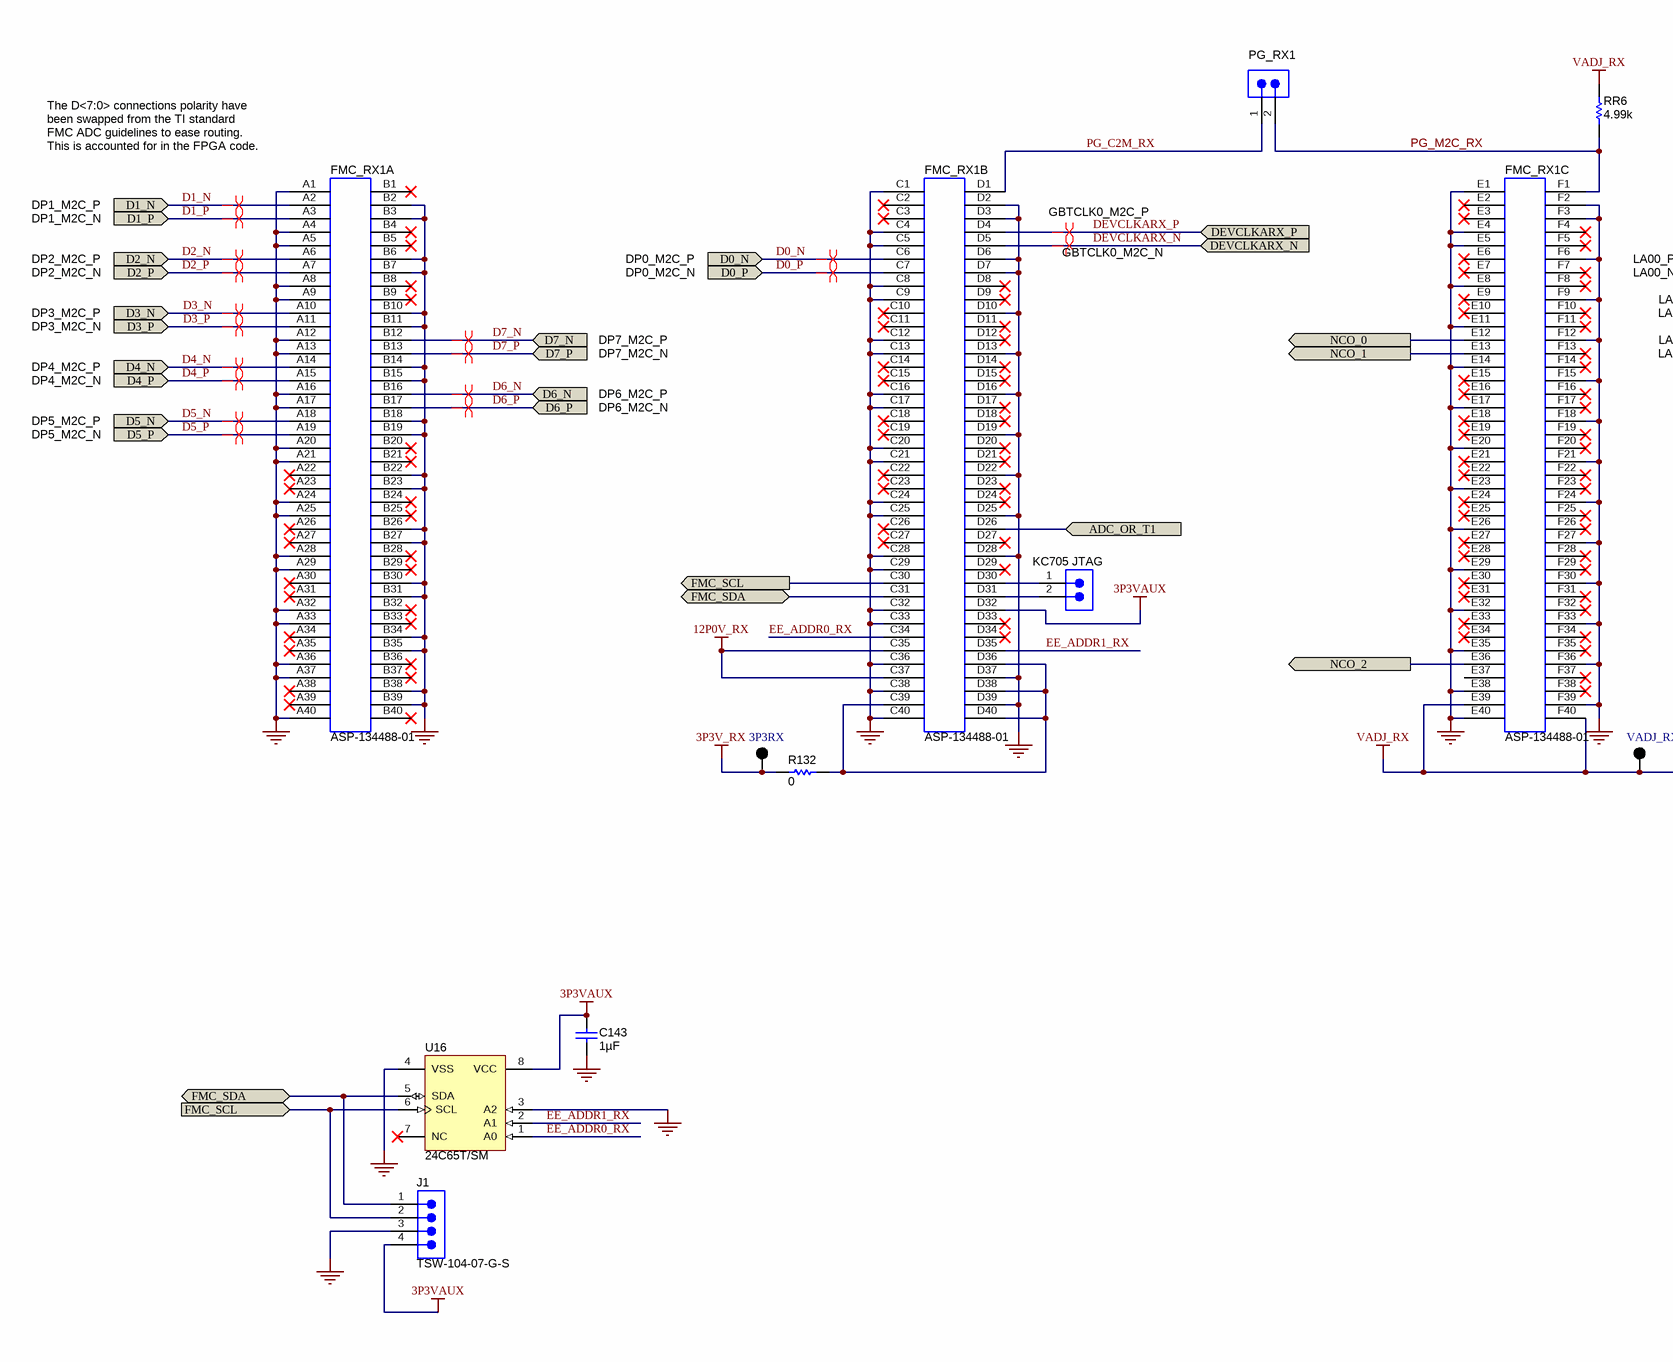
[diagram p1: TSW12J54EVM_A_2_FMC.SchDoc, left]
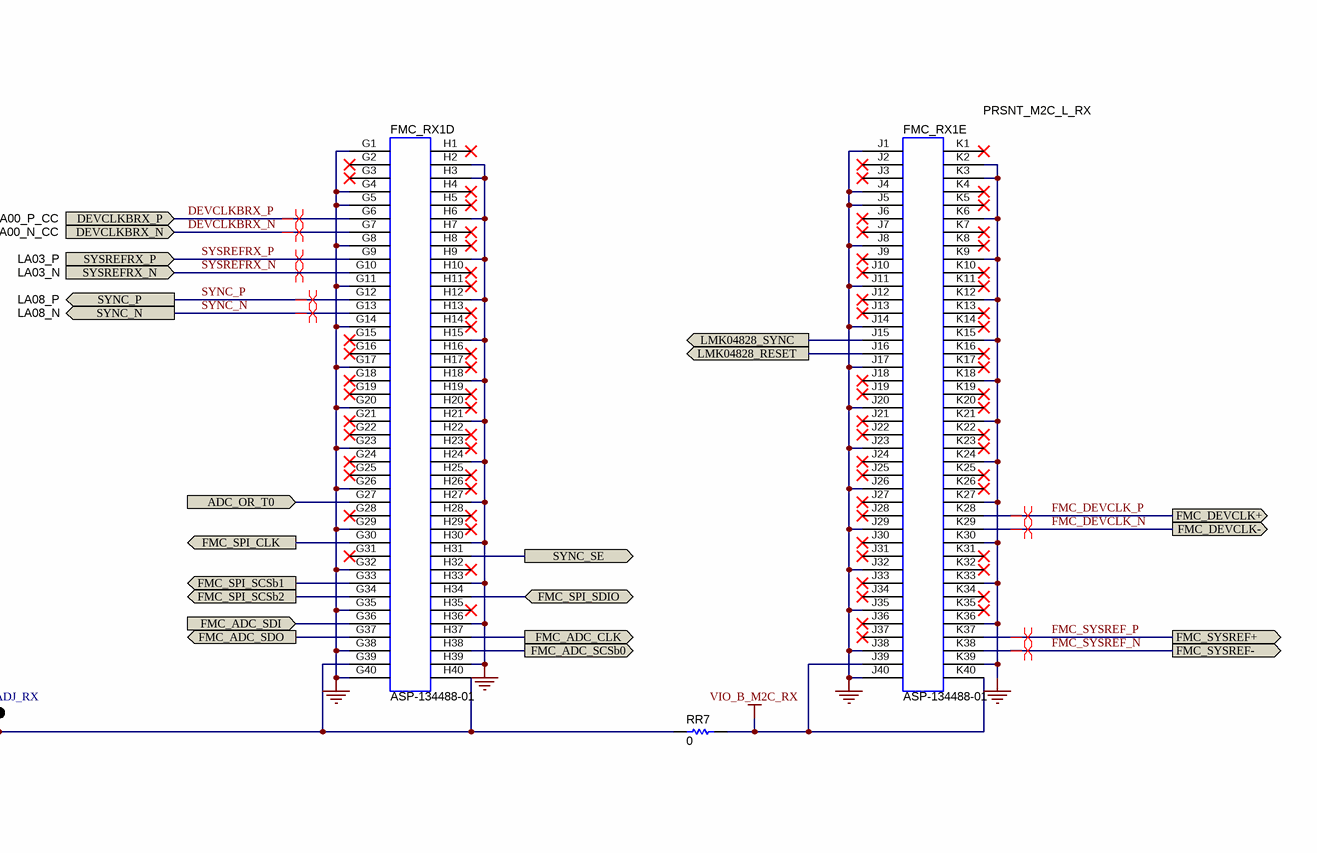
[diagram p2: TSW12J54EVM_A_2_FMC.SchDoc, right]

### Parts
3P3RX  5011  [Keystone5011]  (value not drawn)
C143  ValueDisplayed: 1µF  [0603L]  (hidden comment: C1608X5R1A105K)
FMC_RX1  ASP-134488-01  [CONN_SEARAY_ASP-134488-01]  (parts A,B,C,D,E of 5)
J1  TSW-104-07-G-S  [TSW-104-07-G-S]
KC705_JTAG  TSW-102-07-G-S  [TSW-102-07-G-S]  (value not drawn)
PG_RX1  TSW-102-07-G-S  [TSW-102-07-G-S]  (value not drawn)
R132  value 0  [0603L]  (hidden comment: CRCW06030000Z0EA)
RR6  value 4.99k  [0603L]  (hidden comment: CRCW06034K99FKEA)
RR7  value 0  [0603L]  (hidden comment: ERJ-3GEY0R00V)
U16  24C65T/SM  [SOIJ-SM8_N]
VADJ_RX  5011  [Keystone5011]  (value not drawn)

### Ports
ADC_OR_T0 (in), ADC_OR_T1 (in), D0_N (in), D0_P (in), D1_N (in), D1_P (in), D2_N (in), D2_P (in), D3_N (in), D3_P (in), D4_N (in), D4_P (in), D5_N (in), D5_P (in), D6_N (in), D6_P (in), D7_N (in), D7_P (in), DEVCLKARX_N (in), DEVCLKARX_P (in), DEVCLKBRX_N (in), DEVCLKBRX_P (in), FMC_ADC_CLK (out), FMC_ADC_SCSb0 (out), FMC_ADC_SDI (in), FMC_ADC_SDO (out), FMC_DEVCLK+ (out), FMC_DEVCLK- (out), FMC_SCL (in), FMC_SCL (out), FMC_SDA (bidir), FMC_SPI_CLK (out), FMC_SPI_SCSb1 (out), FMC_SPI_SCSb2 (out), FMC_SPI_SDIO (bidir), FMC_SYSREF+, FMC_SYSREF-, LMK04828_RESET (out), LMK04828_SYNC (out), NCO_0 (out), NCO_1 (out), NCO_2 (out), SYNC_N (out), SYNC_P (out), SYNC_SE (out), SYSREFRX_N (in), SYSREFRX_P (in)

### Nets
3P3V_RX: 3P3RX.1 R132.1
3P3VAUX: C143.1 FMC_RX1.D32 J1.4 U16.8(VCC)
12P0V_RX: FMC_RX1.C35 FMC_RX1.C37
GND: C143.2 FMC_RX1.A1 FMC_RX1.A4 FMC_RX1.A5 FMC_RX1.A8 FMC_RX1.A9 FMC_RX1.A12 FMC_RX1.A13 FMC_RX1.A16 FMC_RX1.A17 FMC_RX1.A20 FMC_RX1.A21 FMC_RX1.A24 FMC_RX1.A25 FMC_RX1.A28 FMC_RX1.A29 FMC_RX1.A32 FMC_RX1.A33 FMC_RX1.A36 FMC_RX1.A37 FMC_RX1.A40 FMC_RX1.B2 FMC_RX1.B3 FMC_RX1.B6 FMC_RX1.B7 FMC_RX1.B10 FMC_RX1.B11 FMC_RX1.B14 FMC_RX1.B15 FMC_RX1.B18 FMC_RX1.B19 FMC_RX1.B22 FMC_RX1.B23 FMC_RX1.B26 FMC_RX1.B27 FMC_RX1.B30 FMC_RX1.B31 FMC_RX1.B34 FMC_RX1.B35 FMC_RX1.B38 FMC_RX1.B39 FMC_RX1.C1 FMC_RX1.C4 FMC_RX1.C5 FMC_RX1.C8 FMC_RX1.C9 FMC_RX1.C12 FMC_RX1.C13 FMC_RX1.C16 FMC_RX1.C17 FMC_RX1.C20 FMC_RX1.C21 FMC_RX1.C24 FMC_RX1.C25 FMC_RX1.C28 FMC_RX1.C29 FMC_RX1.C32 FMC_RX1.C33 FMC_RX1.C36 FMC_RX1.C38 FMC_RX1.C40 FMC_RX1.D2 FMC_RX1.D3 FMC_RX1.D6 FMC_RX1.D7 FMC_RX1.D10 FMC_RX1.D13 FMC_RX1.D16 FMC_RX1.D19 FMC_RX1.D22 FMC_RX1.D25 FMC_RX1.D28 FMC_RX1.D37 FMC_RX1.D39 FMC_RX1.E1 FMC_RX1.E4 FMC_RX1.E5 FMC_RX1.E8 FMC_RX1.E11 FMC_RX1.E14 FMC_RX1.E17 FMC_RX1.E20 FMC_RX1.E23 FMC_RX1.E26 FMC_RX1.E29 FMC_RX1.E32 FMC_RX1.E35 FMC_RX1.E38 FMC_RX1.E40 FMC_RX1.F2 FMC_RX1.F3 FMC_RX1.F6 FMC_RX1.F9 FMC_RX1.F12 FMC_RX1.F15 FMC_RX1.F18 FMC_RX1.F21 FMC_RX1.F24 FMC_RX1.F27 FMC_RX1.F30 FMC_RX1.F33 FMC_RX1.F36 FMC_RX1.F39 FMC_RX1.G1 FMC_RX1.G4 FMC_RX1.G5 FMC_RX1.G8 FMC_RX1.G11 FMC_RX1.G14 FMC_RX1.G17 FMC_RX1.G20 FMC_RX1.G23 FMC_RX1.G26 FMC_RX1.G29 FMC_RX1.G32 FMC_RX1.G35 FMC_RX1.G38 FMC_RX1.G40 FMC_RX1.H2 FMC_RX1.H3 FMC_RX1.H6 FMC_RX1.H9 FMC_RX1.H12 FMC_RX1.H15 FMC_RX1.H18 FMC_RX1.H21 FMC_RX1.H24 FMC_RX1.H27 FMC_RX1.H30 FMC_RX1.H33 FMC_RX1.H36 FMC_RX1.H39 FMC_RX1.J1 FMC_RX1.J4 FMC_RX1.J5 FMC_RX1.J8 FMC_RX1.J11 FMC_RX1.J14 FMC_RX1.J17 FMC_RX1.J20 FMC_RX1.J23 FMC_RX1.J26 FMC_RX1.J29 FMC_RX1.J32 FMC_RX1.J35 FMC_RX1.J38 FMC_RX1.J40 FMC_RX1.K2 FMC_RX1.K3 FMC_RX1.K6 FMC_RX1.K9 FMC_RX1.K12 FMC_RX1.K15 FMC_RX1.K18 FMC_RX1.K21 FMC_RX1.K24 FMC_RX1.K27 FMC_RX1.K30 FMC_RX1.K33 FMC_RX1.K36 FMC_RX1.K39 J1.3 U16.3(A2) U16.4(VSS)
VADJ_RX: FMC_RX1.E39 FMC_RX1.F40 FMC_RX1.G39 FMC_RX1.H40 RR6.2 RR7.1 VADJ_RX.1
VIO_B_M2C_RX: FMC_RX1.J39 FMC_RX1.K40 RR7.2
ADC_OR_T0: FMC_RX1.G27 ; port ADC_OR_T0
ADC_OR_T1: FMC_RX1.D26 ; port ADC_OR_T1
D0_N: FMC_RX1.C6 ; port D0_N
D0_P: FMC_RX1.C7 ; port D0_P
D1_N: FMC_RX1.A2 ; port D1_N
D1_P: FMC_RX1.A3 ; port D1_P
D2_N: FMC_RX1.A6 ; port D2_N
D2_P: FMC_RX1.A7 ; port D2_P
D3_N: FMC_RX1.A10 ; port D3_N
D3_P: FMC_RX1.A11 ; port D3_P
D4_N: FMC_RX1.A14 ; port D4_N
D4_P: FMC_RX1.A15 ; port D4_P
D5_N: FMC_RX1.A18 ; port D5_N
D5_P: FMC_RX1.A19 ; port D5_P
D6_N: FMC_RX1.B16 ; port D6_N
D6_P: FMC_RX1.B17 ; port D6_P
D7_N: FMC_RX1.B12 ; port D7_N
D7_P: FMC_RX1.B13 ; port D7_P
DEVCLKARX_N: FMC_RX1.D5 ; port DEVCLKARX_N
DEVCLKARX_P: FMC_RX1.D4 ; port DEVCLKARX_P
DEVCLKBRX_N: FMC_RX1.G7 ; port DEVCLKBRX_N
DEVCLKBRX_P: FMC_RX1.G6 ; port DEVCLKBRX_P
EE_ADDR0_RX: FMC_RX1.C34 U16.1(A0)
EE_ADDR1_RX: FMC_RX1.D35 U16.2(A1)
FMC_DEVCLK_N: FMC_RX1.K29 ; port FMC_DEVCLK-
FMC_DEVCLK_P: FMC_RX1.K28 ; port FMC_DEVCLK+
FMC_SYSREF_N: FMC_RX1.K38 ; port FMC_SYSREF-
FMC_SYSREF_P: FMC_RX1.K37 ; port FMC_SYSREF+
LMK04828_RESET: FMC_RX1.J16 ; port LMK04828_RESET
LMK04828_SYNC: FMC_RX1.J15 ; port LMK04828_SYNC
PG_C2M_RX: FMC_RX1.D1 PG_RX1.1
PG_M2C_RX: FMC_RX1.F1 PG_RX1.2 RR6.1
SYNC_N: FMC_RX1.G13 ; port SYNC_N
SYNC_P: FMC_RX1.G12 ; port SYNC_P
SYNC_SE: FMC_RX1.H31 ; port SYNC_SE
SYSREFRX_N: FMC_RX1.G10 ; port SYSREFRX_N
SYSREFRX_P: FMC_RX1.G9 ; port SYSREFRX_P
NetFMC_RX1_C30: FMC_RX1.C30 J1.2 U16.6(SCL) ; port FMC_SCL
NetFMC_RX1_C31: FMC_RX1.C31 J1.1 U16.5(SDA) ; port FMC_SDA
NetFMC_RX1_C39: FMC_RX1.C39 FMC_RX1.D36 FMC_RX1.D38 FMC_RX1.D40 R132.2
NetFMC_RX1_D30: FMC_RX1.D30 KC705_JTAG.1
NetFMC_RX1_D31: FMC_RX1.D31 KC705_JTAG.2
NetFMC_RX1_E12: FMC_RX1.E12 ; port NCO_0
NetFMC_RX1_E13: FMC_RX1.E13 ; port NCO_1
NetFMC_RX1_E36: FMC_RX1.E36 ; port NCO_2
NetFMC_RX1_G30: FMC_RX1.G30 ; port FMC_SPI_CLK
NetFMC_RX1_G33: FMC_RX1.G33 ; port FMC_SPI_SCSb1
NetFMC_RX1_G34: FMC_RX1.G34 ; port FMC_SPI_SCSb2
NetFMC_RX1_G36: FMC_RX1.G36 ; port FMC_ADC_SDI
NetFMC_RX1_G37: FMC_RX1.G37 ; port FMC_ADC_SDO
NetFMC_RX1_H34: FMC_RX1.H34 ; port FMC_SPI_SDIO
NetFMC_RX1_H37: FMC_RX1.H37 ; port FMC_ADC_CLK
NetFMC_RX1_H38: FMC_RX1.H38 ; port FMC_ADC_SCSb0

Not connected (* = marked no-connect by the designer): FMC_RX1 A22* A23* A26* A27* A30* A31* A34* A35* A38* A39* B1* B4* B5* B8* B9* B20* B21* B24* B25* B28* B29* B32* B33* B36* B37* B40* C2* C3* C10* C11* C14* C15* C18* C19* C22* C23* C26* C27* D8* D9* D11* D12* D14* D15* D17* D18* D20* D21* D23* D24* D27* D29* D33* D34* E2* E3* E6* E7* E9* E10* E15* E16* E18* E19* E21* E22* E24* E25* E27* E28* E30* E31* E33* E34* E37 F4* F5* F7* F8* F10* F11* F13* F14* F16* F17* F19* F20* F22* F23* F25* F26* F28* F29* F31* F32* F34* F35* F37* F38* G2* G3* G15* G16* G18* G19* G21* G22* G24* G25* G28* G31* H1* H4* H5* H7* H8* H10* H11* H13* H14* H16* H17* H19* H20* H22* H23* H25* H26* H28* H29* H32* H35* J2* J3* J6* J7* J9* J10* J12* J13* J18* J19* J21* J22* J24* J25* J27* J28* J30* J31* J33* J34* J36* J37* K1* K4* K5* K7* K8* K10* K11* K13* K14* K16* K17* K19* K20* K22* K23* K25* K26* K31* K32* K34* K35*; U16 7(NC)*

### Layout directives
differential pair: D0_N, D0_P, D1_N, D1_P, D2_N, D2_P, D3_N, D3_P, D4_N, D4_P, D5_N, D5_P, D6_N, D6_P, D7_N, D7_P, DEVCLKARX_N, DEVCLKARX_P, DEVCLKBRX_N, DEVCLKBRX_P, FMC_DEVCLK_N, FMC_DEVCLK_P, FMC_SYSREF_N, FMC_SYSREF_P, SYNC_N, SYNC_P, SYSREFRX_N, SYSREFRX_P

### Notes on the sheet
- The D<7:0> connections polarity have been swapped from the TI standard FMC ADC guidelines to ease routing.  This is accounted for in the FPGA code.
- PRSNT_M2C_L_RX
- DP1_M2C_P
- DP1_M2C_N
- GBTCLK0_M2C_P
- DP2_M2C_P
- DP2_M2C_N
- DP0_M2C_P
- DP0_M2C_N
- GBTCLK0_M2C_N
- LA00_P_CC
- LA00_N_CC
- DP3_M2C_P
- DP3_M2C_N
- DP7_M2C_P
- DP7_M2C_N
- LA03_P
- LA03_N
- LA08_P
- LA08_N
- DP4_M2C_P
- DP4_M2C_N
- DP5_M2C_P
- DP6_M2C_P
- DP6_M2C_N
- DP5_M2C_N

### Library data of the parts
3P3RX VADJ_RX = 5011: Test Point, TH, Multipurpose, Black; Manufacturer: Keystone Electronics; CompType: Test Point Loop
C143 = C1608X5R1A105K: as C39 on sheet TSW12J54EVM_A_1_ADC_IO
FMC_RX1 = ASP-134488-01: Connector, Receptacle, 400-Pos (40x10), 50x50-mil Pitch, SMT; Manufacturer: Molex; Alternate PartNumber: 45970-4315; SymbolCreator: a0799721; U/M: EA
J1 = TSW-104-07-G-S: Header, TH, 100mil, 4x1, Gold plated, 230 mil above insulator; Manufacturer: Samtec, Inc.; SymbolCreator: a0412235; U/M: EA
KC705_JTAG PG_RX1 = TSW-102-07-G-S: as EXT_Vcmo on sheet TSW12J54EVM_A_1_ADC_IO
R132 = CRCW06030000Z0EA: RES, 0 ohm, 5%, 0.1W, 0603; Manufacturer: Vishay-Dale; CompType: Resistor; Value_Code: 0000; Tolerance_%: 5; Power_W: 0.1; VDC_V: 75; TempCo: 200 ppm/C; EIA_Code: E24; U/M: EA
RR6 = CRCW06034K99FKEA: RES, 4.99k ohm, 1%, 0.1W, 0603; Manufacturer: Vishay-Dale; CompType: Resistor; Res_ohm: 4990; Value_Code: 4k99; Tolerance_%: 1; Power_W: 0.1; VDC_V: 75; TempCo: 100 ppm/C; EIA_Code: E96; U/M: EA
RR7 = ERJ-3GEY0R00V: as R99 on sheet TSW12J54EVM_A_1_ADC_IO
U16 = 24C65T/SM: 64Kbit, 400kHz, 4.5V, I2C Serial EEPROM, 8-Pin SOIC 208mil, Commercial Temperature, Tape and Reel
